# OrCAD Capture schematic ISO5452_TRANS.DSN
size D
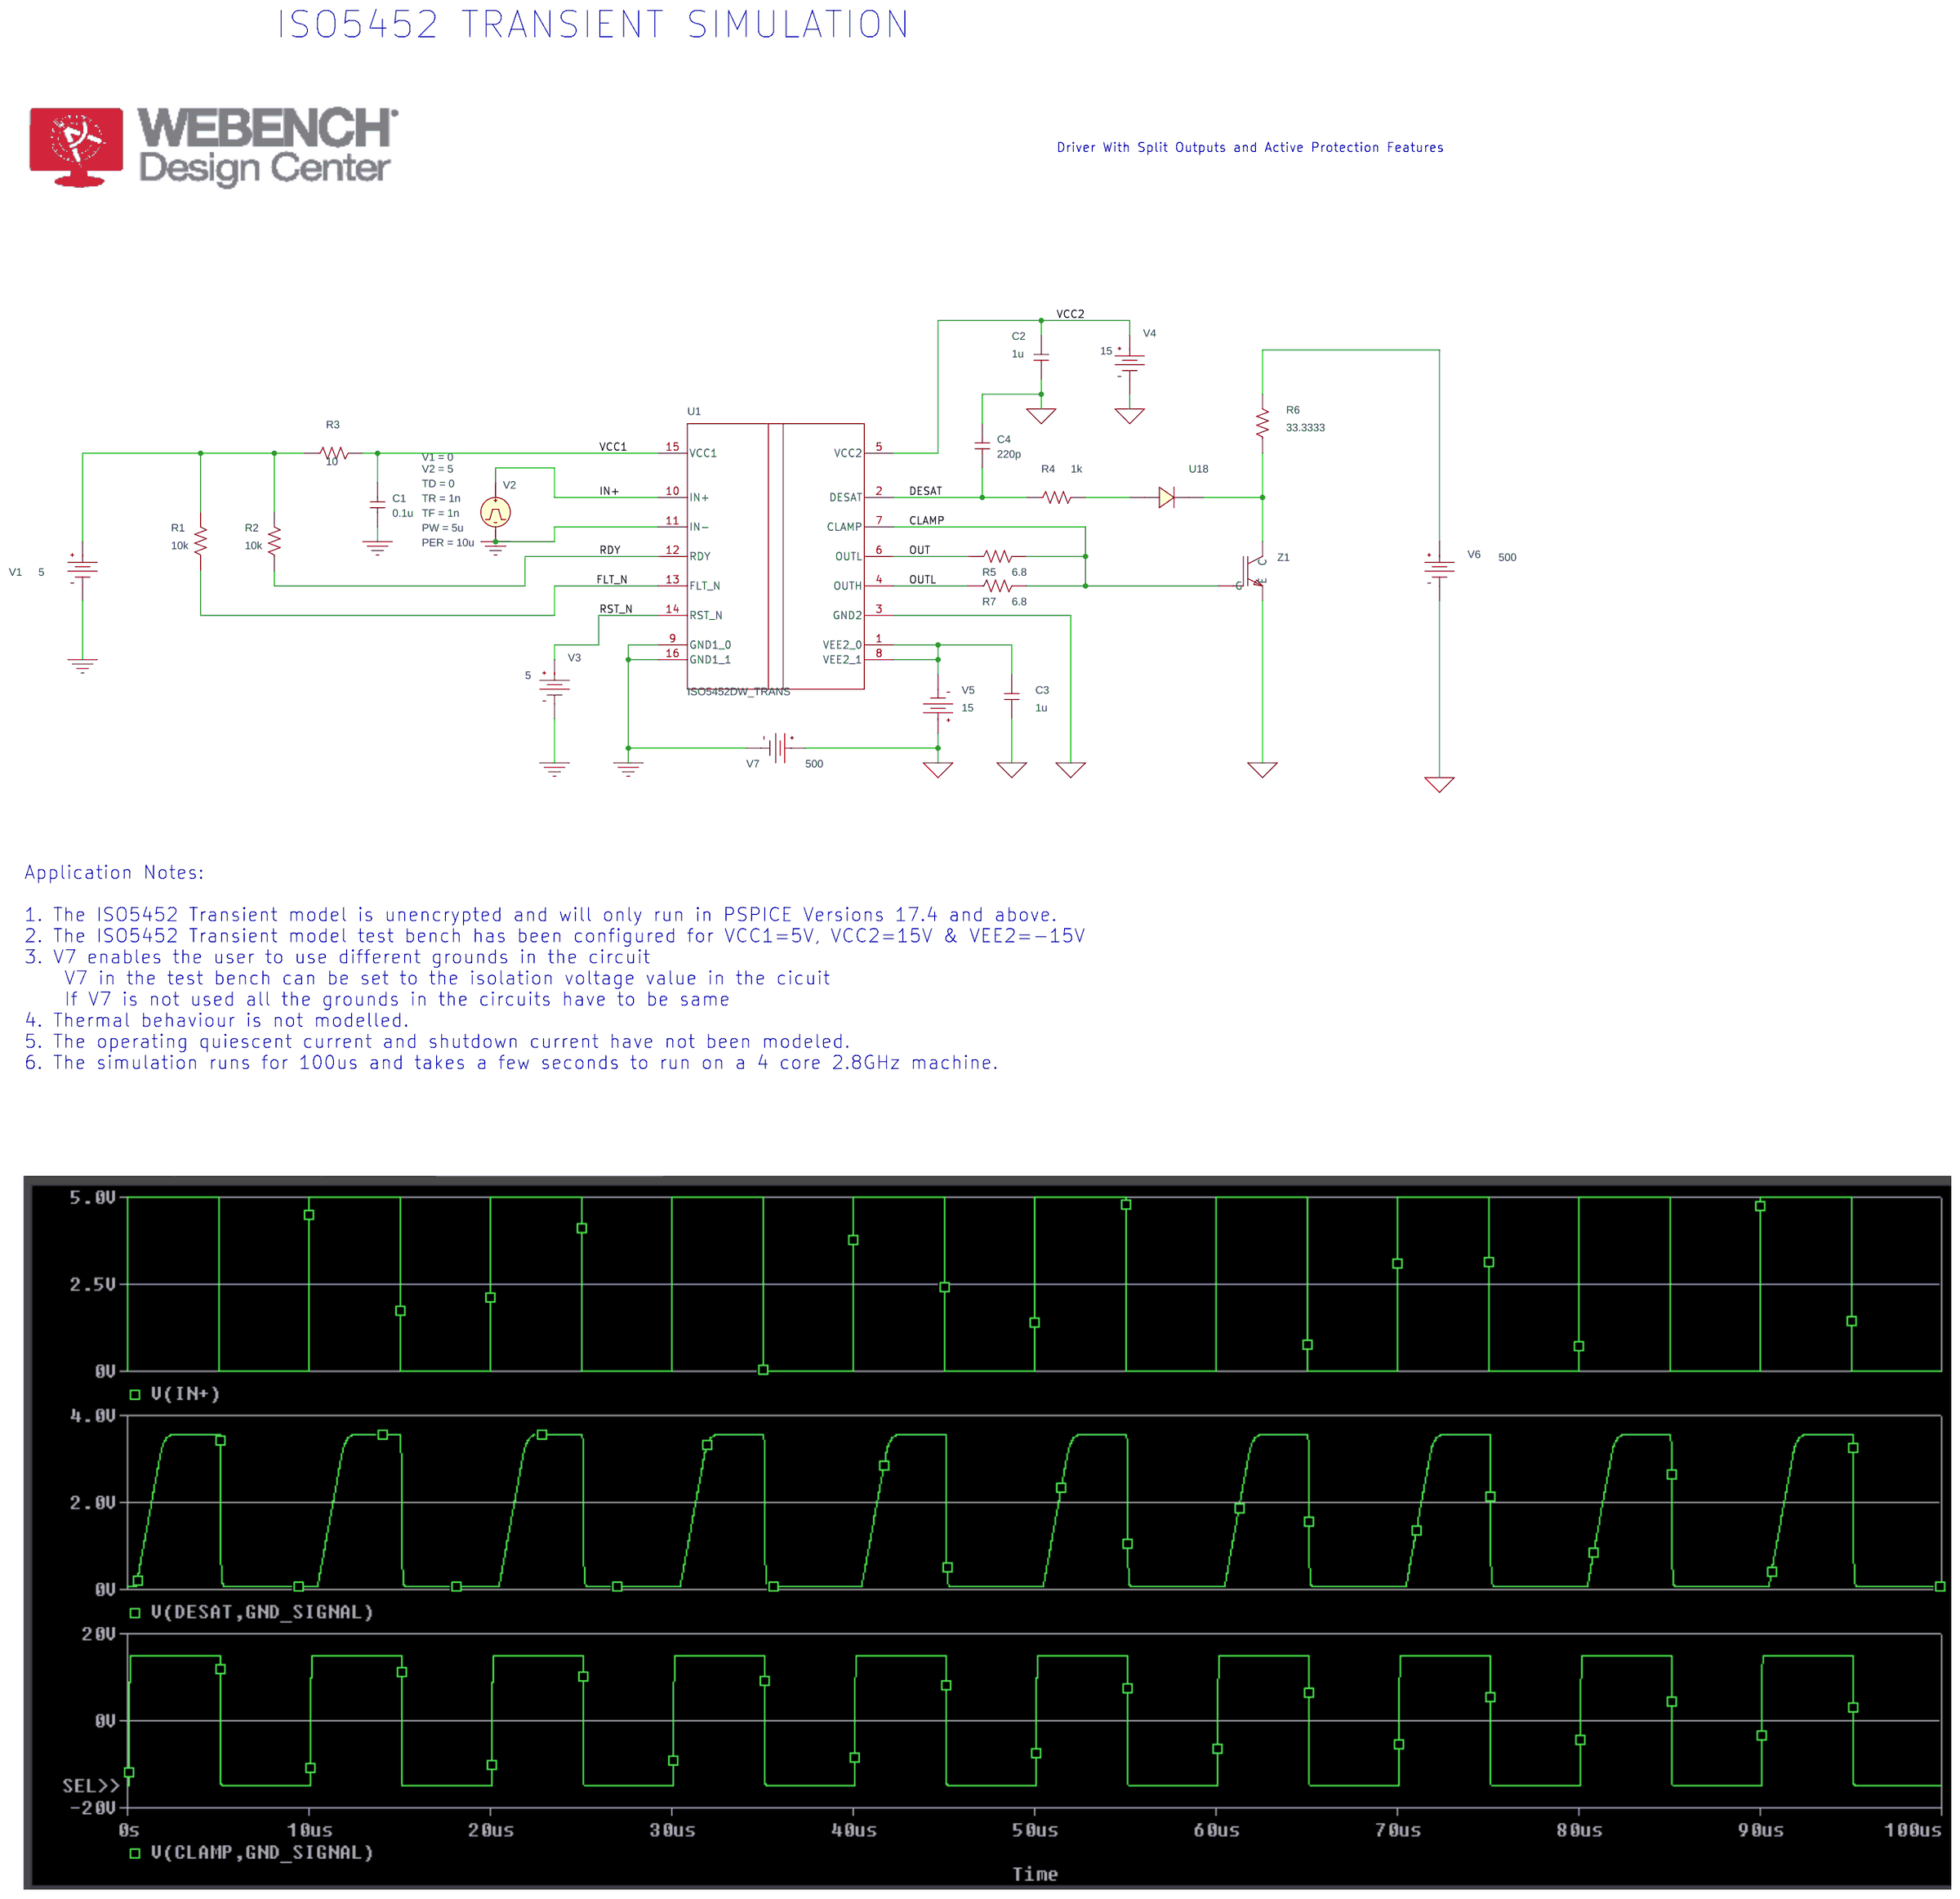
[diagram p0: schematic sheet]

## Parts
C1  0.1u  [RAD/CK05]
C2  1u  [RAD/CK05]
C3  1u  [RAD/CK05]
C4  220p  [RAD/CK05]
R1  10k  [AX/RC05]
R2  10k  [AX/RC05]
R3  10  [AX/RC05]
R4  1k  [AX/RC05]
R5  6.8  [AX/RC05]
R6  33.3333  [AX/RC05]
R7  6.8  [AX/RC05]
U1  ISO5452DW_TRANS  [DW0016B_N]
U18  D_D1
V1  VDC
V2  VPULSE
V3  VDC
V4  VDC
V5  VDC
V6  VDC
V7  VDC
Z1  IXGA8N100  [TO-263]

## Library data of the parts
C1-C4 = C
R1-R7 = R
U1 = ISO5452DW_TRANS
U18 = D_D1
V1 V3 = VDC: DC: 5
V2 = VPULSE: PER: 10u; PW: 5u; TD: 0; TF: 1n; TR: 1n; V1: 0; V2: 5
V4 V5 = VDC: DC: 15
V6 V7 = VDC: DC: 500
Z1 = IXGA8N100

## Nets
GND_SIGNAL: C2.1 C3.1 C4.2 U1.3(GND2) V4.1(-) V5.0(+) V6.1(-) V7.0(+) Z1.3(E)
VCC1: C1.2 R3.2 U1.15(VCC1)
VCC2: C2.2 U1.5(VCC2) V4.0(+)
0: C1.1 U1.9(GND1_0) U1.11(IN-) U1.16(GND1_1) V1.1(-) V2.2(-) V3.1(-) V7.1(-)
CLAMP: R5.2 R7.2 U1.7(CLAMP) Z1.1(G)
DESAT: C4.1 R4.1 U1.2(DESAT)
FLT_N: R1.1 U1.13(FLT_N)
IN+: U1.10(IN+) V2.1(+)
OUT: R5.1 U1.6(OUTL)
OUTL: R7.1 U1.4(OUTH)
RDY: R2.1 U1.12(RDY)
RST_N: U1.14(RST_N) V3.0(+)
N16731106: R1.2 R2.2 R3.1 V1.0(+)
N16731342: R6.1 U18.2 Z1.2(C)
N16731354: C3.2 U1.1(VEE2_0) U1.8(VEE2_1) V5.1(-)
N16731676: R4.2 U18.1
N16731822: R6.2 V6.0(+)

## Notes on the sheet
- ISO5452 TRANSIENT SIMULATION
- Driver With Split Outputs and Active Protection Features
- Application Notes:
  1. The ISO5452 Transient model is unencrypted and will only run in PSPICE Versions 17.4 and above.
  2. The ISO5452 Transient model test bench has been configured for VCC1=5V, VCC2=15V & VEE2=-15V
  3. V7 enables the user to use different grounds in the circuit
      V7 in the test bench can be set to the isolation voltage value in the cicuit
      If V7 is not used all the grounds in the circuits have to be same
  4. Thermal behaviour is not modelled.
  5. The operating quiescent current and shutdown current have not been modeled.
  6. The simulation runs for 100us and takes a few seconds to run on a 4 core 2.8GHz machine.
